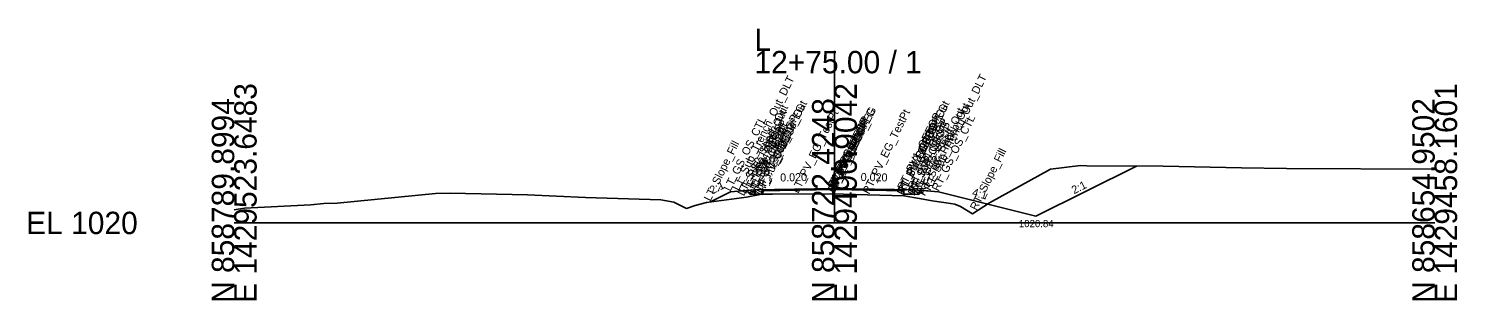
# Model space of a CAD drawing. Extents: x -26 to 153, y -10 to 13058.
# Drawn here: x -25.7 to 152.8, y 2490.3 to 2524.3 of the extents above; entities that cross this region are included whole.
import ezdxf

# ---------------------------------------------------------------- set-up
doc = ezdxf.new("R2010")
doc.units = 0
for name, color, linetype in [('Default', 7, 'Continuous'), ('Exist Cross Section Cell', 7, 'Continuous'), ('Exist XS Ground Line', 7, 'Continuous'), ('Prop CMT Pvmt Course 1', 7, 'Continuous'), ('Prop CMT Pvmt Course 1 Wedge', 7, 'Continuous'), ('Prop CMT Pvmt Surface', 7, 'Continuous'), ('Prop CMT Pvmt Surface Shoulder', 7, 'Continuous'), ('Prop CMT Pvmt Wedge Surface 1', 7, 'Continuous'), ('Prop CMT Shld Paved Course 1', 7, 'Continuous'), ('Prop CMT Slope Grass', 7, 'Continuous'), ('Prop CMT Subgrade Earthwork', 7, 'Continuous'), ('Prop XS Dump Level', 7, 'Continuous'), ('Prop XS SE Text', 7, 'Continuous'), ('Prop XS Side Slope Text', 7, 'Continuous')]:
    doc.layers.add(name, color=color, linetype=linetype)

msp = doc.modelspace()

# ---------------------------------------------------------------- linework, layer by layer
at = {"layer": 'Exist Cross Section Cell'}
for p, q in [((75, 2500), (75, 2521.51)), ((0, 2500), (75, 2500)), ((75, 2500), (150, 2500))]:
    msp.add_line(p, q, dxfattribs=at)
at = {"layer": 'Exist XS Ground Line'}
msp.add_lwpolyline([(0, 2501.63), (1.28, 2501.83), (9.57, 2502.27), (11.2, 2502.43), (12.85, 2502.47), (25.15, 2503.67), (27, 2503.72), (36.65, 2503.51), (43.88, 2503.19), (53.32, 2502.88), (54.93, 2502.61), (56.53, 2501.81), (57.6, 2502.2), (59.02, 2502.57), (63.99, 2503.24), (65.94, 2503.6), (67.24, 2503.61), (74.69, 2503.65), (75, 2503.64), (76.15, 2503.61), (83.67, 2503.37), (85.63, 2503.04), (87.2, 2502.77), (88.94, 2502.51), (90.06, 2502.33), (90.74, 2502.06), (92.23, 2501.14), (94.36, 2502.52), (102.01, 2506.74), (105.73, 2507.17), (106.54, 2507.15), (116.08, 2507.11), (125.87, 2506.9), (131.47, 2506.82), (150, 2506.72)], dxfattribs=at)
at = {"layer": 'Prop CMT Pvmt Course 1'}
for points in [[(75, 2504.32), (65, 2504.12)], [(65, 2504.12), (65, 2503.58)], [(65, 2503.58), (65.94, 2503.6)], [(65.94, 2504.01), (75, 2504.19)], [(65.94, 2503.6), (65.94, 2504.01)], [(75, 2503.78), (75, 2504.32)], [(75, 2504.32), (85, 2504.12)], [(75, 2503.78), (75, 2504.32)], [(75, 2504.19), (75, 2503.78), (75, 2503.78)], [(83.67, 2504.02), (75, 2504.19)], [(75, 2504.19), (75, 2503.78), (75, 2503.78)], [(83.67, 2503.6), (83.67, 2504.02)], [(85, 2503.58), (83.67, 2503.6)], [(85, 2504.12), (85, 2503.58)]]:
    msp.add_lwpolyline(points, dxfattribs=at)
at = {"layer": 'Prop CMT Pvmt Course 1 Wedge'}
for points in [[(65.94, 2504.01), (65.94, 2504.01), (67.24, 2504.04), (74.69, 2504.19), (75, 2504.19)], [(65.94, 2503.6), (65.94, 2504.01)], [(75, 2503.64), (74.69, 2503.65), (67.24, 2503.61), (65.94, 2503.6), (65.94, 2503.6)], [(75, 2504.19), (75, 2503.64)], [(75, 2504.19), (76.15, 2504.17), (83.67, 2504.02)], [(75, 2503.64), (75, 2504.19)], [(83.67, 2503.37), (76.15, 2503.61), (75, 2503.64)], [(83.67, 2504.02), (83.67, 2503.37)]]:
    msp.add_lwpolyline(points, dxfattribs=at)
at = {"layer": 'Prop CMT Pvmt Surface'}
for points in [[(75, 2504.32), (65, 2504.12)], [(75, 2504.32), (85, 2504.12)]]:
    msp.add_lwpolyline(points, dxfattribs=at)
at = {"layer": 'Prop CMT Pvmt Surface Shoulder'}
for points in [[(65, 2504.12), (65, 2504.12)], [(85, 2504.12), (85, 2504.12)]]:
    msp.add_lwpolyline(points, dxfattribs=at)
at = {"layer": 'Prop CMT Pvmt Wedge Surface 1'}
for points in [[(65, 2503.58), (65, 2504.12)], [(65.94, 2503.6), (65, 2503.58)], [(75, 2504.19), (65.94, 2504.01)], [(65.94, 2504.01), (65.94, 2503.6)], [(75, 2504.19), (83.67, 2504.02)], [(83.67, 2504.02), (83.67, 2503.6)], [(83.67, 2503.6), (85, 2503.58)], [(85, 2503.58), (85, 2504.12)]]:
    msp.add_lwpolyline(points, dxfattribs=at)
at = {"layer": 'Prop CMT Shld Paved Course 1'}
for points in [[(65, 2504.12), (64.45, 2503.57)], [(64.45, 2503.57), (65, 2503.58)], [(65, 2504.12), (65, 2504.12)], [(65, 2503.58), (65, 2504.12)], [(85, 2504.12), (85, 2504.12)], [(85, 2504.12), (85.55, 2503.57)], [(85, 2503.58), (85, 2504.12)], [(85.55, 2503.57), (85, 2503.58)]]:
    msp.add_lwpolyline(points, dxfattribs=at)
at = {"layer": 'Prop CMT Slope Grass'}
for p, q in [((100.17, 2500.84), (112.75, 2507.12)), ((88, 2503.88), (100.17, 2500.84))]:
    msp.add_line(p, q, dxfattribs=at)
for points in [[(65, 2504.12), (62, 2503.88), (59.51, 2502.64)], [(85, 2504.12), (88, 2503.88), (88, 2503.88)]]:
    msp.add_lwpolyline(points, dxfattribs=at)
at = {"layer": 'Prop CMT Subgrade Earthwork'}
for points in [[(64.45, 2503.57), (63.98, 2504.04)], [(65, 2503.58), (64.45, 2503.57)], [(65.94, 2503.6), (65, 2503.58)], [(65.94, 2503.6), (65.96, 2503.6)], [(83.67, 2503.6), (83.65, 2503.37)], [(83.67, 2503.6), (85, 2503.58)], [(85, 2503.58), (85.55, 2503.57)], [(85.55, 2503.57), (86.02, 2504.04)]]:
    msp.add_lwpolyline(points, dxfattribs=at)

# ---------------------------------------------------------------- texts
at = {"layer": 'Default'}
for s, height, p in [('-', 0.0001, (0, 2500)), ('1020.84', 0.9, (98.04, 2499.47))]:
    msp.add_text(s, height=height, dxfattribs=at).set_placement(p)
at = {"layer": 'Exist Cross Section Cell'}
for s, p in [('L', (65, 2521.51)), ('12+75.00 / 1', (65, 2518.71)), ('EL 1020', (-26, 2498.6))]:
    msp.add_text(s, height=2.8, dxfattribs=at).set_placement(p)
for s, p in [('E 1429523.6483', (2.8, 2490)), ('E 1429490.9042', (77.8, 2490)), ('E 1429458.1601', (152.8, 2490)), ('N 858789.8994', (0, 2490)), ('N 858722.4248', (75, 2490)), ('N 858654.9502', (150, 2490))]:
    msp.add_text(s, height=2.8, rotation=90, dxfattribs=at).set_placement(p)
at = {"layer": 'Prop XS Dump Level'}
for s, p in [('LT_Sub_Trench_Out_DLT', (63.03, 2503.96)), ('RT_Sub_Trench_Out_DLT', (86.97, 2503.96)), ('LT_Sub_Trench_Out', (63.69, 2503.3)), ('LT_PS2_Shelf_Out', (63.95, 2503.56)), ('LT_PV_OEEOP_EG', (65.94, 2503.6)), ('LT_PV_Sub_Tie_Out', (65.96, 2503.6)), ('LT_PV_EG_TestPt', (70.47, 2503.63)), ('RT_PV_IEEOP_EG', (75, 2503.64)), ('LT_PV_IEEOP_EG', (75, 2503.64)), ('RT_PV_EG_TestPt', (79.33, 2503.51)), ('RT_PV_Sub_Tie_Out', (83.65, 2503.37)), ('RT_PV_OEEOP_EG', (83.67, 2503.37)), ('RT_PV1_OEEOP', (83.67, 2504.02)), ('RT_PS2_Shelf_Out', (86.05, 2503.56)), ('RT_Sub_Trench_Out', (86.31, 2503.3)), ('LT_GS_OS_CTL', (62, 2503.88)), ('LT_PS2_OEOP', (64.45, 2503.57)), ('LT_PV1_OEOT', (65, 2504.12)), ('LT_PS1_OEOP', (65, 2504.12)), ('LT_PV2_OEOT', (65, 2503.58)), ('LT_Sub_OEOT', (65, 2503.33)), ('LT_PV1_OEEOP', (65.94, 2504.01)), ('LT_PV2_OEEOP', (65.94, 2503.6)), ('LT_Sub_OEEOP', (65.94, 2503.35)), ('RT_PV1_IEEOP', (75, 2504.19)), ('LT_PV1_IEEOP', (75, 2504.19)), ('RT_PV2_IEEOP', (75, 2503.78)), ('LT_PV2_IEEOP', (75, 2503.78)), ('RT_PV2_OEEOP', (83.67, 2503.6)), ('RT_Sub_OEEOP', (83.67, 2503.35)), ('RT_PV1_OEOT', (85, 2504.12)), ('RT_PS1_OEOP', (85, 2504.12)), ('RT_PV2_OEOT', (85, 2503.58)), ('RT_Sub_OEOT', (85, 2503.33)), ('RT_PS2_OEOP', (85.55, 2503.57)), ('RT_GS_OS_CTL', (88, 2503.88)), ('LT_Slope_Fill', (59.51, 2502.64)), ('PV1_PGL', (75, 2504.32)), ('PV2_PGL', (75, 2503.78)), ('RT_Slope_Fill', (92.77, 2501.49))]:
    msp.add_text(s, height=1, rotation=63.5833, dxfattribs=at).set_placement(p)
at = {"layer": 'Prop XS SE Text'}
for rotation, p in [(1.1458, (68.23, 2505.18)), (358.8542, (78.27, 2505.25))]:
    msp.add_text('0.020', height=1, rotation=rotation, dxfattribs=at).set_placement(p)
at = {"layer": 'Prop XS Side Slope Text'}
for s, rotation, p in [('2:1', 26.5651, (59.71, 2503.57)), ('2:1', 26.5651, (104.94, 2503.59)), ('4:1', 345.9638, (92.14, 2503.39))]:
    msp.add_text(s, height=1, rotation=rotation, dxfattribs=at).set_placement(p)

doc.saveas('drawing.dxf')
